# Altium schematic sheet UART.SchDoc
size A; SheetNumber: 4; SheetTotal: 6
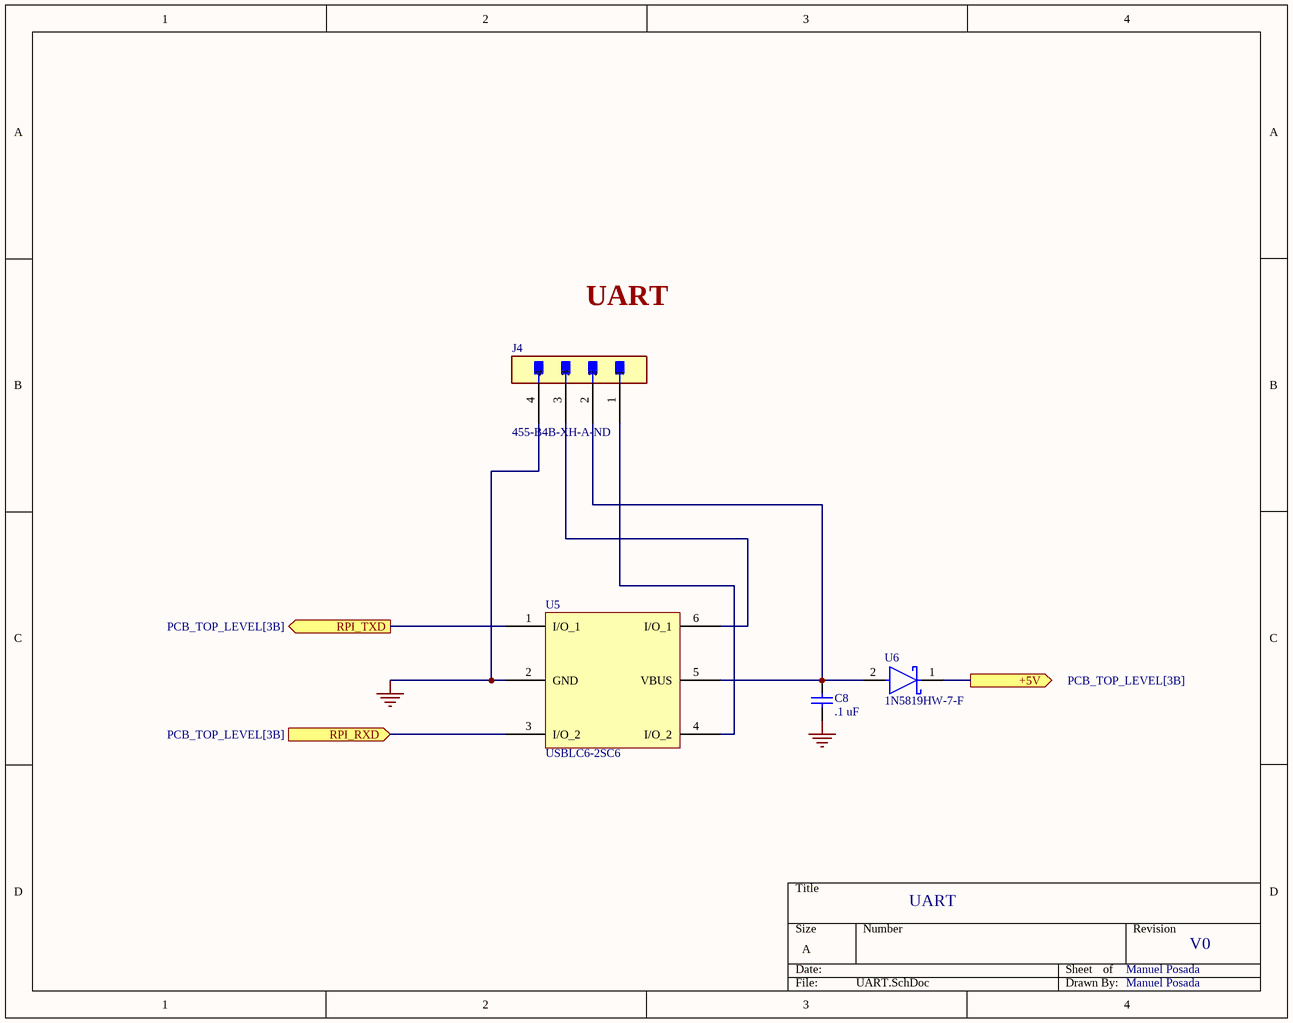
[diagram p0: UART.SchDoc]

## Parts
C8  .1 uF  [CAP_CL21_SAM-L]
J4  455-B4B-XH-A-ND  [CONN_B4B-XH-A_JST]
U5  USBLC6-2SC6  [SOT23-6L_STM]
U6  1N5819HW-7-F  [FP-SOD123-IPC_B]

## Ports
+5V (out, see PCB_TOP_LEVEL[3B]), RPI_RXD (in, see PCB_TOP_LEVEL[3B]), RPI_TXD (out, see PCB_TOP_LEVEL[3B])

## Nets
GND: C8.1 J4.4 U5.2(GND)
+5V: U6.1(C) ; port +5V
RPI_RXD: U5.3(I/O_2) ; port RPI_RXD
RPI_TXD: U5.1(I/O_1) ; port RPI_TXD
NetC8_2: C8.2 J4.2 U5.5(VBUS) U6.2(A)
NetJ4_1: J4.1 U5.4(I/O_2)
NetJ4_3: J4.3 U5.6(I/O_1)

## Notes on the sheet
- UART
- Manuel Posada
- V0

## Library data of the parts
C8 = CL21B104KBCNNNC: 50V 100nF X7R ±10% 0805 Multilayer Ceramic Capacitors MLCC - SMD/SMT ROHS; Manufacturer: Samsung Electro-Mechanics
J4 = B4B-XH-A: Board Connector, 4 Contact(s), 1 Row(s), Male, Straight, Solder Terminal; Manufacturer: JST; Contact Resistance: 20mΩ; Current Rating: 3A; Insulation Resistance: 1GΩ
U5 = USBLC6-2SC6: 17V Clamp 5A (8/20µs) Ipp Tvs Diode Surface Mount SOT-23-6; Manufacturer: STMicroelectronics; Breakdown Voltage: 6V; Value: 2.5pF; Data Rate: 480Mbps; Direction: Unidirectional; Element Configuration: Dual; ESD Protection: Yes; Forward Voltage: 1.1V; Leakage Current: 150nA; Max Junction Temperature (Tj): 125°C; Max Repetitive Reverse Voltage (Vrrm): 5.25V; Number of Bidirectional Channels: 2; Number of Elements: 1; Reverse Standoff Voltage: 5V; Test Current: 1mA
U6 = 1N5819HW-7-F: DIODE SCHOTTKY 40V 1A SOD123; Manufacturer: Diodes Inc.; Value: 50pF; Element Configuration: Single; Forward Voltage: 750mV; Max Forward Surge Current (Ifsm): 25A; Max Junction Temperature (Tj): 125°C; Max Power Dissipation: 450mW; Number of Elements: 1; Peak Reverse Current: 1mA; Polarity: Standard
